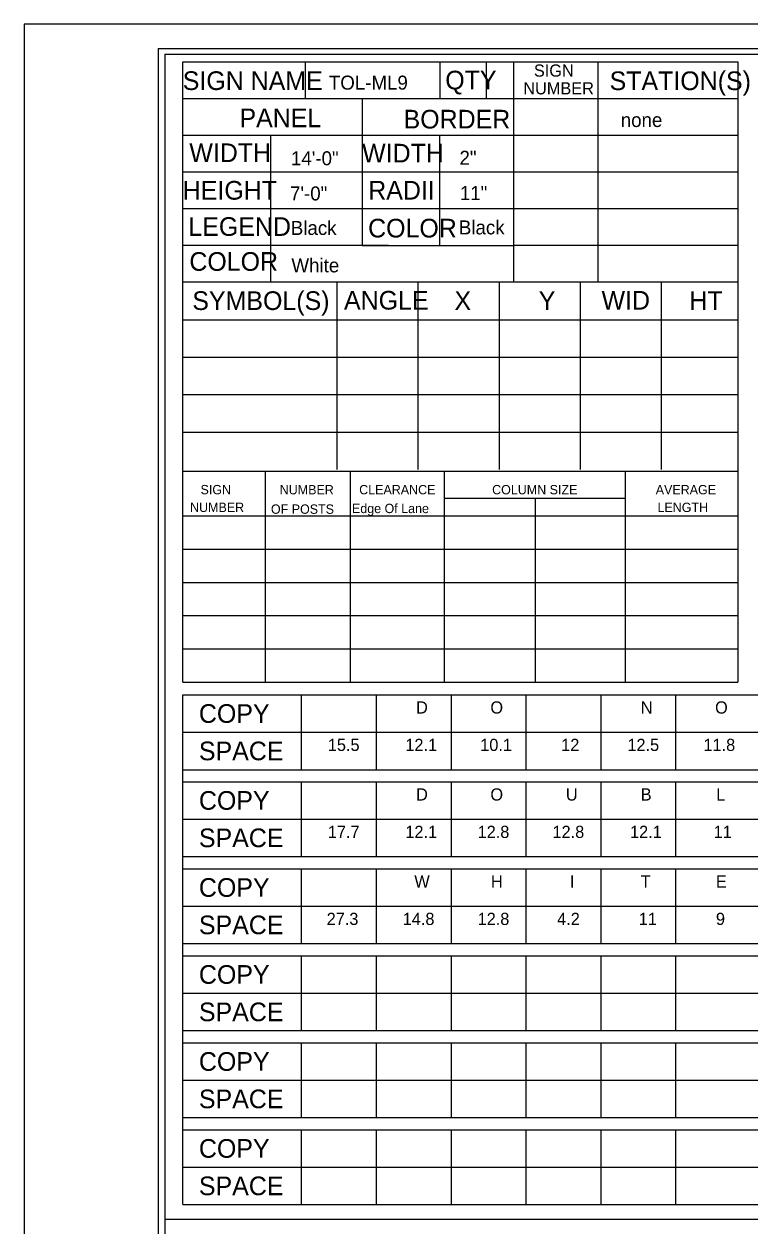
# Model space of a CAD drawing. Extents: x 121688 to 126625, y -22764 to -19972.
# Drawn here: x 125072.6 to 125352.7, y -22217.9 to -21754.2 of the extents above; entities that cross this region are included whole.
import ezdxf

# ---------------------------------------------------------------- set-up
doc = ezdxf.new("R2010")
doc.units = 0
for name, color, linetype in [('GSSign', 7, 'Continuous'), ('PlotBorder_dp', 7, 'Continuous'), ('SheetBorder_dp', 7, 'Continuous'), ('SheetLinesMisc2_dp', 7, 'Continuous'), ('TextMinor', 7, 'Continuous')]:
    doc.layers.add(name, color=color, linetype=linetype)

msp = doc.modelspace()

# ---------------------------------------------------------------- linework, layer by layer
at = {"layer": 'PlotBorder_dp'}
msp.add_lwpolyline([(125072.61, -22751.63), (126625.18, -22751.63), (126625.18, -21754.22), (125072.61, -21754.22)], close=True, dxfattribs=at)
at = {"layer": 'SheetBorder_dp'}
for q in [(125124.37, -22742.22), (126573.42, -21763.63)]:
    msp.add_line((125124.37, -21763.63), q, dxfattribs=at)
at = {"layer": 'SheetLinesMisc2_dp'}
for p, q in [((125126.93, -21765.86), (126571.13, -21765.86)), ((125126.93, -21765.86), (125126.93, -22664.86)), ((125133.86, -22008.11), (125133.86, -21768.85)), ((125133.86, -21768.85), (125348, -21768.85)), ((125181.06, -21768.85), (125181.06, -21782.98)), ((125233.11, -21768.85), (125233.11, -21782.98)), ((125250.9, -21768.85), (125250.9, -21782.98)), ((125261.49, -21768.85), (125261.49, -21853.65)), ((125294.08, -21768.85), (125294.08, -21853.65)), ((125348, -21768.85), (125348, -22008.11)), ((125133.86, -21782.98), (125348, -21782.98)), ((125203.07, -21782.98), (125203.07, -21839.66)), ((125133.86, -21797.12), (125348, -21797.12)), ((125167.7, -21797.12), (125167.7, -21853.65)), ((125232.93, -21797.27), (125232.93, -21839.66)), ((125133.86, -21811.25), (125348, -21811.25)), ((125133.86, -21825.38), (125348, -21825.38)), ((125133.86, -21839.51), (125213.28, -21839.51)), ((125203.07, -21839.66), (125261.49, -21839.66)), ((125261.49, -21839.51), (125348, -21839.51)), ((125133.86, -21853.65), (125348, -21853.65)), ((125193.33, -21853.93), (125193.33, -21926.08)), ((125224.62, -21853.93), (125224.62, -21926.08)), ((125255.91, -21853.93), (125255.91, -21926.08)), ((125287.19, -21853.93), (125287.19, -21926.08)), ((125318.48, -21853.93), (125318.48, -21926.08)), ((125133.91, -21868.36), (125348, -21868.36)), ((125133.91, -21882.79), (125348, -21882.79)), ((125133.91, -21897.21), (125348, -21897.21)), ((125133.91, -21911.65), (125348, -21911.65)), ((125133.86, -21926.77), (125348, -21926.77)), ((125165.63, -21926.77), (125165.63, -22008.11)), ((125198.48, -21926.77), (125198.48, -22008.11)), ((125234.74, -21926.77), (125234.74, -22008.11)), ((125304.58, -21926.77), (125304.58, -22008.11)), ((125234.74, -21937.11), (125304.53, -21937.11)), ((125269.8, -21937.11), (125269.8, -22008.11)), ((125133.86, -21944.01), (125348, -21944.01)), ((125133.86, -21956.83), (125348, -21956.83)), ((125133.86, -21969.65), (125348, -21969.65)), ((125133.86, -21982.47), (125348, -21982.47)), ((125133.86, -21995.29), (125348, -21995.29)), ((125133.86, -22008.11), (125348, -22008.11)), ((125133.86, -22013.04), (125844.12, -22013.04)), ((125133.86, -22209.69), (125133.86, -22013.04)), ((125179.58, -22013.04), (125179.58, -22041.9)), ((125208.48, -22013.04), (125208.48, -22041.9)), ((125237.37, -22013.04), (125237.37, -22041.9)), ((125266.26, -22013.04), (125266.26, -22041.9)), ((125295.15, -22013.04), (125295.15, -22041.9)), ((125324.04, -22013.04), (125324.04, -22041.9)), ((125133.86, -22027.46), (125844.12, -22027.46)), ((125133.86, -22041.9), (125844.12, -22041.9)), ((125133.86, -22046.6), (125844.12, -22046.6)), ((125179.58, -22046.6), (125179.58, -22075.45)), ((125208.48, -22046.6), (125208.48, -22075.45)), ((125237.37, -22046.6), (125237.37, -22075.45)), ((125266.26, -22046.6), (125266.26, -22075.45)), ((125295.15, -22046.6), (125295.15, -22075.45)), ((125324.04, -22046.6), (125324.04, -22075.45)), ((125133.86, -22061.03), (125844.12, -22061.02)), ((125133.86, -22075.45), (125844.12, -22075.45)), ((125133.86, -22080.16), (125844.12, -22080.16)), ((125179.58, -22080.16), (125179.58, -22109.01)), ((125208.48, -22080.16), (125208.48, -22109.01)), ((125237.37, -22080.16), (125237.37, -22109.01)), ((125266.26, -22080.16), (125266.26, -22109.01)), ((125295.15, -22080.16), (125295.15, -22109.01)), ((125324.04, -22080.16), (125324.04, -22109.01)), ((125133.86, -22094.59), (125844.12, -22094.59)), ((125133.86, -22109.01), (125844.12, -22109.01)), ((125133.86, -22113.72), (125844.12, -22113.72)), ((125179.58, -22113.72), (125179.58, -22142.58)), ((125208.48, -22113.72), (125208.48, -22142.58)), ((125237.37, -22113.72), (125237.37, -22142.58)), ((125266.26, -22113.72), (125266.26, -22142.58)), ((125295.15, -22113.72), (125295.15, -22142.58)), ((125324.04, -22113.72), (125324.04, -22142.58)), ((125133.86, -22128.15), (125844.12, -22128.15)), ((125133.86, -22142.58), (125844.12, -22142.58)), ((125133.86, -22147.28), (125844.12, -22147.28)), ((125179.58, -22147.28), (125179.58, -22176.14)), ((125208.48, -22147.28), (125208.48, -22176.14)), ((125237.37, -22147.28), (125237.37, -22176.14)), ((125266.26, -22147.28), (125266.26, -22176.14)), ((125295.15, -22147.28), (125295.15, -22176.14)), ((125324.04, -22147.28), (125324.04, -22176.14)), ((125133.86, -22161.71), (125844.12, -22161.71)), ((125133.86, -22176.14), (125844.12, -22176.14)), ((125133.86, -22180.84), (125844.12, -22180.84)), ((125179.58, -22180.84), (125179.58, -22209.69)), ((125208.48, -22180.84), (125208.48, -22209.69)), ((125237.37, -22180.84), (125237.37, -22209.69)), ((125266.26, -22180.84), (125266.26, -22209.69)), ((125295.15, -22180.84), (125295.15, -22209.69)), ((125324.04, -22180.84), (125324.04, -22209.69)), ((125133.86, -22195.26), (125844.12, -22195.26)), ((125133.86, -22209.69), (125844.12, -22209.69)), ((125126.93, -22215.36), (126571.13, -22215.36))]:
    msp.add_line(p, q, dxfattribs=at)

# ---------------------------------------------------------------- texts
at = {"layer": 'GSSign'}
for s, height, p in [('TOL-ML9', 5.399, (125190.23, -21779.53)), ('none', 5.399, (125302.87, -21793.95)), ('14\'-0"', 5.399, (125175.62, -21808.72)), ('2"', 5.399, (125240.64, -21808.52)), ('7\'-0"', 5.399, (125175.25, -21822.28)), ('11"', 5.399, (125240.78, -21822.13)), ('Black', 5.399, (125175.56, -21835.6)), ('Black', 5.399, (125240.41, -21835.39)), ('White', 5.399, (125175.8, -21850.03)), ('D', 4.71, (125223.89, -22020.25)), ('O', 4.71, (125252.57, -22020.25)), ('N', 4.71, (125310.59, -22020.25)), ('O', 4.71, (125339.27, -22020.25)), ('15.5', 4.705, (125189.84, -22034.68)), ('12.1', 4.705, (125219.75, -22034.68)), ('10.1', 4.705, (125248.65, -22034.68)), ('12', 4.705, (125279.9, -22034.68)), ('12.5', 4.705, (125305.44, -22034.68)), ('11.8', 4.705, (125334.79, -22034.68)), ('D', 4.71, (125223.89, -22053.81)), ('O', 4.71, (125252.57, -22053.81)), ('U', 4.71, (125281.69, -22053.81)), ('B', 4.71, (125310.59, -22053.81)), ('L', 4.71, (125339.72, -22053.81)), ('17.7', 4.705, (125189.84, -22068.24)), ('12.1', 4.705, (125219.75, -22068.24)), ('12.8', 4.705, (125247.64, -22068.24)), ('12.8', 4.705, (125276.54, -22068.24)), ('12.1', 4.705, (125306.45, -22068.24)), ('11', 4.705, (125338.71, -22068.24)), ('W', 4.71, (125223.22, -22087.38)), ('H', 4.71, (125252.79, -22087.38)), ('I', 4.71, (125283.26, -22087.38)), ('T', 4.71, (125310.59, -22087.38)), ('E', 4.71, (125339.6, -22087.38)), ('27.3', 4.705, (125189.39, -22101.81)), ('14.8', 4.705, (125218.74, -22101.81)), ('12.8', 4.705, (125247.64, -22101.81)), ('4.2', 4.705, (125278.33, -22101.81)), ('11', 4.705, (125309.81, -22101.81)), ('9', 4.71, (125339.6, -22101.81))]:
    msp.add_text(s, height=height, dxfattribs=at).set_placement(p)
at = {"layer": 'TextMinor'}
for s, height, p in [('SIGN', 4.705, (125269.36, -21774.52)), ('SIGN NAME', 7.199, (125133.86, -21779.67)), ('QTY', 7.199, (125235.16, -21779.44)), ('STATION(S)', 7.199, (125298.57, -21779.71)), ('NUMBER', 4.705, (125265.26, -21781.36)), ('PANEL', 7.199, (125155.75, -21794.03)), ('BORDER', 7.199, (125219.07, -21794.52)), ('WIDTH', 7.199, (125136.4, -21807.48)), ('WIDTH', 7.199, (125203.07, -21807.63)), ('HEIGHT', 7.199, (125133.86, -21821.97)), ('RADII', 7.199, (125205.43, -21821.94)), ('LEGEND', 7.199, (125136.03, -21835.95)), ('COLOR', 7.199, (125205.38, -21836.56)), ('COLOR', 7.199, (125136.4, -21849.43)), ('SYMBOL(S)', 7.199, (125137.55, -21864.54)), ('ANGLE', 7.199, (125196.08, -21864.39)), ('X', 7.2, (125238.7, -21864.54)), ('Y', 7.2, (125271.23, -21864.54)), ('WID', 7.199, (125295.46, -21864.39)), ('HT', 7.199, (125329.38, -21864.52)), ('SIGN', 3.6, (125140.72, -21935.65)), ('NUMBER', 3.6, (125171.29, -21935.69)), ('CLEARANCE', 3.6, (125201.94, -21935.66)), ('COLUMN SIZE', 3.5997, (125253.24, -21935.66)), ('AVERAGE', 3.6, (125316.37, -21935.66)), ('NUMBER', 3.6, (125136.69, -21942.49)), ('OF POSTS', 3.6, (125167.89, -21943.17)), ('Edge Of Lane', 3.5997, (125199.16, -21942.91)), ('LENGTH', 3.6, (125317.05, -21942.49)), ('COPY', 7.199, (125140.09, -22023.83)), ('SPACE', 7.199, (125140.09, -22038.26)), ('COPY', 7.199, (125140.09, -22057.36)), ('SPACE', 7.199, (125140.09, -22071.79)), ('COPY', 7.199, (125140.09, -22090.95)), ('SPACE', 7.199, (125140.09, -22105.38)), ('COPY', 7.199, (125140.09, -22124.51)), ('SPACE', 7.199, (125140.09, -22138.94)), ('COPY', 7.199, (125140.09, -22158.08)), ('SPACE', 7.199, (125140.09, -22172.51)), ('COPY', 7.199, (125140.09, -22191.62)), ('SPACE', 7.199, (125140.09, -22206.06))]:
    msp.add_text(s, height=height, dxfattribs=at).set_placement(p)

doc.saveas('drawing.dxf')
